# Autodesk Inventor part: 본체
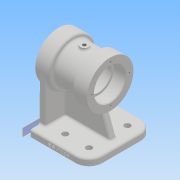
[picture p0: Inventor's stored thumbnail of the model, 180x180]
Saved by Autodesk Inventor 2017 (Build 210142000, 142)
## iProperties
Part Number: 본체
Material: 일반
Document SubType Name: Modeling
Designer: 00-00
Density: 1 g/cm^3
Appearance: 기본값
Mass: 268.673 g
Surface Area: 641.499 cm^2
Volume: 268.673 cm^3
Author: 00-00
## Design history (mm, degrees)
sketch "스케치1"
  geometry: L1 (0, 49)-(90, 49); L2 (90, 49)-(90, -49); L3 (90, -49)-(0, -49); L4 (0, -49)-(0, 49); 2 further points
  constraints: 8 end point, 2 parallel, 1 coincident, 1 horizontal, 1 midpoint, 1 perpendicular
  dimensions: "d0" = 90 distance of L1.start L1.end; "d1" = 98 distance of L1.end L2.end
extrude "돌출1" new body sketch "스케치1" distance "d2" = 10; taper "d3" = 0 deg
node "작업 평면1"
sketch "스케치2"
  geometry: C1 r 35 at (0, 80); 1 further point
  constraints: 1 centre point, 1 vertical alignment
  dimensions: "d5" = 70 diameter of C1; "d6" = 80 distance of point (0, 0) C1.centre
extrude "돌출2" join sketch "스케치2" distance "d7" = 22; taper "d8" = 0 deg
sketch "스케치3"
  geometry: C1 r 35 at (0, 0) reference; C2 r 29 at (0, 0); 1 further point
  constraints: 1 centre point, 1 coincident
  dimensions: "d9" = 58 diameter of C2
extrude "돌출3" join sketch "스케치3" distance "d10" = 34; taper "d11" = 0 deg
sketch "스케치4"
  geometry: C1 r 29 at (0, 0) reference; C2 r 35 at (0, 0); 1 further point
  constraints: 1 centre point, 1 coincident
  dimensions: "d12" = 70 diameter of C2
extrude "돌출4" join sketch "스케치4" distance "d13" = 22; taper "d14" = 0 deg
sketch "스케치5"
  geometry: L1 (0, 35)-(10, 35); L2 (10, 35)-(10, -35); L3 (10, -35)-(0, -35); L4 (0, -35)-(0, 35); L5 (0, 5)-(78, 5); L6 (78, 5)-(78, -5); L7 (78, -5)-(0, -5); L8 (0, -5)-(0, 5); L9 (0, -49)-(0, 49) reference; L10 (90, 49)-(90, -49) reference; 2 further points
  constraints: 16 end point, 4 parallel, 3 midpoint, 2 horizontal, 2 perpendicular
  dimensions: "d15" = 10 distance of L1.start L1.end; "d16" = 10 distance of L5.end L6.end; "d17" = 70 distance of L1.end L2.end; "d18" = 12 distance between parallel lines of L10 L6
extrude "돌출5" join sketch "스케치5" stored distance "d19" = 22; taper "d20" = 0 deg
sketch "스케치6"
  geometry: L1 (-90, 0)-(-90, 10) reference; L2 (-90, 10)-(0, 10) reference; L3 (-17, 115)-(-17, 45) reference; L4 (5, 115)-(5, 45) reference; L5 (0, 80)-(-10, 80) reference; L6 (0, 80)-(0, 80) reference; L7 (0, 80)-(-10, 80) reference; L8 (-10, 80)-(-10, 80) reference; L9 (-51, 109)-(-51, 51) reference; L10 (-17, 51)-(-17, 109) reference; L11 (-73, 115)-(-73, 45) reference; L12 (-51, 45)-(-51, 115) reference; L13 (-78, 10)-(-60.919, 56.929); L14 (-60.919, 56.929)-(-5, 56.929); L15 (-5, 56.929)-(-5, 10); L16 (-5, 10)-(-78, 10); 1 further point
  constraints: 8 end point, 2 perpendicular, 2 point on line
  dimensions: "d21" = 12 distance from line of L13.start L1; "d22" = 70 deg angle of L2 L13; "d23" = 46.92925 distance of L14.end L15.end; "d24" = 55.91915 distance of L13.end L14.end
extrude "돌출6" join sketch "스케치6" stored distance "d25" = 10; taper "d26" = 0 deg
sketch "스케치7"
  geometry: L1 (5, 115)-(5, 45) reference; L2 (-73, 115)-(-73, 45) reference; L3 (5, 80)-(-73, 80); L4 (5, 80)-(-13, 80); L5 (-13, 80)-(-13, 103.2); L6 (-12.7, 103.5)-(5, 103.5); L7 (5, 103.5)-(5, 80); L8 (-13, 80)-(-19, 80); L9 (-19, 80)-(-19, 100); L10 (-19, 100)-(-13, 100); L11 (-13, 100)-(-13, 80); L12 (-19, 80)-(-49, 80); L13 (-49, 80)-(-49, 100); L14 (-46, 103)-(-22, 103); L15 (-19, 100)-(-19, 80); L16 (-73, 80)-(-55, 80); L17 (-55, 80)-(-55, 103.2); L18 (-55.3, 103.5)-(-73, 103.5); L19 (-73, 103.5)-(-73, 80); L20 (-55, 80)-(-49, 80); L21 (-49, 80)-(-49, 100); L22 (-49, 100)-(-55, 100); L23 (-55, 100)-(-55, 80); A1 r 0.3 centre (-12.7, 103.2) between (-12.7, 103.5) and (-13, 103.2); A2 r 0.3 centre (-55.3, 103.2) between (-55, 103.2) and (-55.3, 103.5); A3 r 3 centre (-22, 100) between (-19, 100) and (-22, 103); A4 r 3 centre (-46, 100) between (-46, 103) and (-49, 100); 5 further points
  constraints: 42 end point, 10 parallel, 9 point on line, 8 point on circle, 8 tangent, 5 horizontal, 5 perpendicular, 4 centre point, 2 equal radius, 2 midpoint
  dimensions: "d27" = 18 distance of point (-13, 103.5) L6.end; "d28" = 23.5 distance of L4.end point (-13, 103.5); "d29" = 6 distance of L9.end L10.end; "d30" = 20 distance of L8.end L9.end; "d31" = 30 distance of point (-49, 103) point (-19, 103); "d32" = 23 distance of L12.end point (-49, 103); "d33" = 18 distance of point (-55, 103.5) L18.end; "d34" = 23.5 distance of L16.end point (-55, 103.5); "d35" = 20 distance between parallel lines of L20 L22; "d36" = 0.3 radius of A1; "d37" = 3 radius of A3
revolve "회전1" sketch "스케치7" stored, may be unused: angle "d38" = 90 deg
sketch "스케치8"
  geometry: A1 r 29 centre (0, 0) between (-28.566, -5) and (-28.566, 5) reference; 2 further points
  constraints: 1 horizontal alignment
  dimensions: "d39" = 28.5 distance of A1.centre point (28.5, 0)
hole "구멍1" sketch "스케치8" at (28.5, 0) diameter "d40" = 3.242; stored, may be unused: countersink angle "d44" = 90 deg, drill point angle "d46" = 118 deg; dims "d41" = 10, "d42" = 4, "d43" = 2, "d45" = 12
sketch "스케치9"
  geometry: C1 r 35 at (0, 0) reference; 2 further points
  constraints: 1 horizontal alignment
  dimensions: "d50" = 28.5 distance of C1.centre point (-28.5, 0)
hole "구멍2" sketch "스케치9" at (-28.5, 0) diameter "d51" = 3.242; stored, may be unused: countersink angle "d55" = 90 deg, drill point angle "d57" = 118 deg; dims "d52" = 10, "d53" = 4, "d54" = 2, "d56" = 12
node "작업 평면2"
sketch "스케치10"
  geometry: L1 (-5, -35)-(-5, 35) reference; C1 r 6 at (34, 0); 1 further point
  constraints: 1 centre point, 1 horizontal alignment
  dimensions: "d62" = 39 distance from line of C1.centre L1; "d63" = 12 diameter of C1
extrude "돌출7" join sketch "스케치10" stored distance "d64" = 39 (= d62); taper "d65" = 0 deg
hole "구멍3" diameter "d68" = 5.188; stored, may be unused: countersink angle "d72" = 90 deg, drill point angle "d74" = 118 deg; dims "d66" = 10, "d67" = 10, "d69" = 12, "d70" = 4, "d71" = 2, "d73" = 16
chamfer "모따기1" distance "d75" = 1; stored, may be unused: second distance "d76" = 2, angle "d77" = 45 deg
fillet "모깎기1" dims "d78" = 3
fillet "모깎기2" dims "d79" = 20
sketch "스케치11"
  geometry: L1 (70, -49)-(0, -49) reference; L2 (0, -49)-(0, 49) reference; L3 (0, 49)-(70, 49) reference; L4 (90, 29)-(90, -29) reference; A1 r 20 centre (70, -29) between (70, -49) and (90, -29) reference; A2 r 20 centre (70, 29) between (90, 29) and (70, 49) reference; 5 further points
  constraints: 2 coincident, 2 horizontal alignment
  dimensions: "d80" = 36 distance of point (34, 29) point (70, 29); "d81" = 36 distance of point (34, -29) point (70, -29)
hole "구멍4" sketch "스케치11" at (70, 29), (34, 29), (70, -29), (34, -29) diameter "d82" = 9; stored, may be unused: countersink angle "d86" = 90 deg, drill point angle "d88" = 118 deg; dims "d83" = 12, "d84" = 4, "d85" = 2, "d87" = 16
fillet "모깎기3" dims "d89" = 3
fillet "모깎기4" dims "d90" = 3
fillet "모깎기5" dims "d91" = 3
fillet "모깎기6" dims "d92" = 3
fillet "모깎기7" dims "d93" = 3
fillet "모깎기8" dims "d94" = 3
fillet "모깎기9" dims "d95" = 3
sketch "스케치12"
  geometry: 2 further points
  constraints: 1 other
  dimensions: "d96" = 4 vertical distance of point (-3, 0) point (42, 4); "d97" = 45 horizontal distance of point (-3, 0) point (42, 4)
feature "엠보싱1" sketch "스케치12" dims "d0" = 90, "d1" = 98, "d98" = 0.5, "d99" = 0
node "솔리드1"
pattern_circular "원형 패턴1" dims angle "d48" = 360 deg
pattern_circular "원형 패턴2" dims angle "d59" = 360 deg
node "투영된 루프1"
node "투영된 루프2"
node "투영된 루프3"
node "투영된 루프4"
node "투영된 루프5"
node "투영된 루프6"
other parameters: "d4" = -5, "d61" = 112
